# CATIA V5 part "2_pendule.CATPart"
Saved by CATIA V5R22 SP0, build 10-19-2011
Part number: 2_pendule
Bounding box of the stored display mesh (mm): x -13.4 to 13.4, y -13.391 to 20, z -52 to 20
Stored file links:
  C:\Users\La forge\Desktop\CAO_PER_pick&place_2023A\test_impression\2_pendule.CATPart
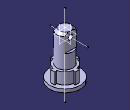
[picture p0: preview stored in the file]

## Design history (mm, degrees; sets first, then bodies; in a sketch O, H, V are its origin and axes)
Body1 (main body)
  Point1: (0, 0, 0)
  Line1: type PtDir, RefPoint Point1, Direction xy-plane, Start -52, End 20
  Line2: type Normal, RefPoint Point1, RefSkin zx-plane, Start -13, End 20
  Sketch1 on yz-plane, origin (0, 0, 0), H (0, 1, 0), V (0, 0, 1)
    point P1 (0, 5)
    line L1 (0, 5) -> (-7, 5)
    line L2 (-9, -32.5) -> (-13.4, -32.5)
    line L3 (-13.4, -32.5) -> (-13.4, -35.5)
    line L4 (-13.4, -35.5) -> (0, -35.5)
    point P5 (0, -35.5)
    line L5 (0, -35.5) -> (0, 5)
    reference projected line E1 (-13, 0) -> (20, 0) from Line2
    reference projected point E2 (0, 0) from Point1
    reference projected line E3 (0, -52) -> (0, 20) from Line1
    line L6 (-7, 5) -> (-7, -22.5)
    line L7 (-7, -22.5) -> (-9, -22.5)
    line L8 (-9, -22.5) -> (-9, -32.5)
    reference projected line E4 (0, -52) -> (0, 20) from Line1
    distance L2 L4 = 3
    distance L1 E1 = 5
    distance E2 L2 = 32.5
    distance L3 E3 = 13.4
    distance L6 E4 = 7
    distance L7 L2 = 10
    distance L8 L5 = 9
    coincidence: P1 V, P5 V
    horizontal: L1 H, L2 H, L4 H, L7 H
    vertical: L3 V, L5 V, L6 V, L8 V
  Shaft1: profile Sketch1, axis Line1, angle 360
  Chamfer1: length 2, angle 45, on edge [face of Shaft1 from Sketch1.L6 | face of Shaft1 from Sketch1.L1]
  Sketch2 on yz-plane, origin (0, 0, 0), H (0, 1, 0), V (0, 0, 1)
    line L1 (-21.1145, 5) -> (-4.85, 5)
    line L2 (-4.85, 5) -> (-4.85, -10)
    line L3 (-4.85, -10) -> (-21.1145, -10)
    line L4 (-21.1145, -10) -> (-21.1145, 5)
    reference projected line E1 (0, -52) -> (0, 20) from Line1
    distance L2 E1 = 4.85
    distance L3 L1 = 15
    horizontal: L1 H, L3 H
    vertical: L2 V, L4 V
  Pocket1: profile Sketch2, direction (-1, 0, 0), through (limit type 6), opposite side through (limit type 6)
  Sketch3 on face of Pocket1 from Sketch2.L2, origin (-3.8766, -4.85, -8.6623), H (1, 0, 0), V (0, 0, 1)
    point P1 (3.8766, 8.6623)
    reference projected point E1 (3.8766, 8.6623) from Point1
    coincidence: P1 E1
  Hole1: placed by Sketch3, at (0, -4.85, 0) direction (0, 1, 0), diameter 4.2, through (limit type 3)
  Sketch4 on face of Shaft1 from Sketch1.L2, origin (0, 0, -32.5), H (1, 0, 0), V (0, 1, 0)
    arc A1 centre (0, 0) radius 11.05 from (1.9188, 10.8821) to (-1.9188, 10.8821) ccw
    point P1 (0, 0)
    reference projected point E1 (0, 0) from Point1
    arc A2 centre (0, 0) radius 9 from (1.5628, 8.8633) to (-1.5628, 8.8633) ccw
    point P2 (0, 0)
    reference projected point E2 (0, 0) from Point1
    axis line L1 (0, 0) -> (3.4021, 19.2943)
    point P3 (0, 0)
    reference projected point E3 (0, 0) from Point1
    reference projected line E4 (0, -13) -> (0, 20) from Line2
    point P5 (1.9188, 10.8821)
    point P6 (1.8117, 6.7615)
    line L2 (1.9188, 10.8821) -> (1.5628, 8.8633)
    point P7 (1.9188, 10.8821)
    point P8 (1.5628, 8.8633)
    reference projected line E5 (0, -13) -> (0, 20) from edge of Line2
    point P11 (-1.5628, 8.8633)
    point P12 (-1.9188, 10.8821)
    line L3 (-1.9188, 10.8821) -> (-1.5628, 8.8633)
    point P13 (1.9188, 10.8821)
    point P14 (1.5628, 8.8633)
    reference projected point E6 (0, 0) from Point1
    reference projected circle E7 centre (0, 0) radius 9 from edge [face of Shaft1 from Sketch1.L8 | face of Shaft1 from Sketch1.L7]
    angle L1 E4 = 10
    radius A1 = 11.05
    coincidence: P1 E1, E2 P2, E3 L1, P5 A1, P5 L1, P7 P5, L1 P13, P3 E6, P8 P14, P8 L1, A2 E7
    symmetry: P8 P11 E5, P7 P12 E5, L2 L3 E5
  Pad1: profile Sketch4, direction (0, 0, 1), up to face of Shaft1 from Sketch1.L7
  CircPattern1: of Pad1, instances 4, angular step 90 {= 360.0*1 deg/CircPattern1.AngularNumber}, axis from Line1
  Mirror1: of Pocket1, about zx-plane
